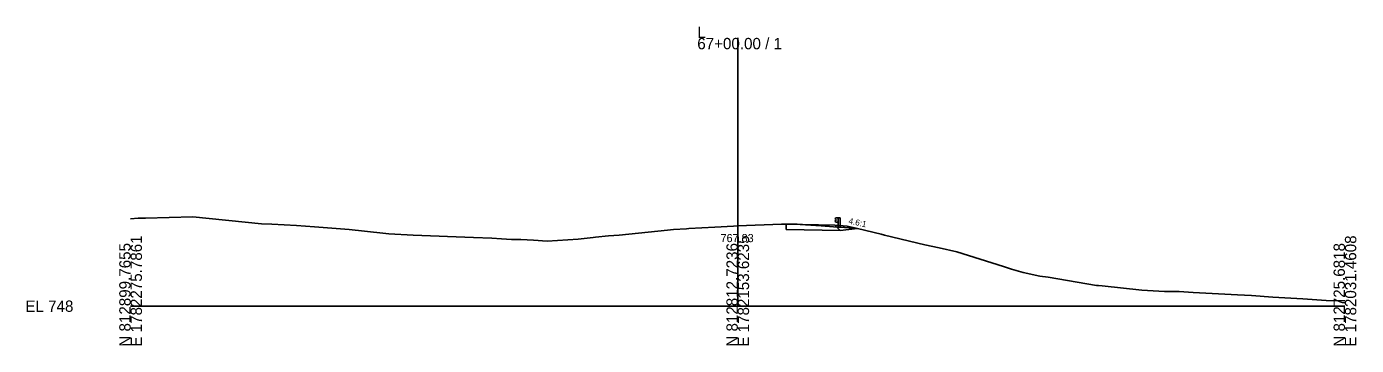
# Model space of a CAD drawing. Extents: x -26 to 7903, y -10 to 9573.
# Drawn here: x 2974.3 to 3302.8, y 7990.3 to 8069.1 of the extents above; entities that cross this region are included whole.
import ezdxf

# ---------------------------------------------------------------- set-up
doc = ezdxf.new("R2010")
doc.units = 0
for name, color, linetype in [('Exist Cross Section Cell', 7, 'Continuous'), ('Exist XS Center Line Elevation Label', 7, 'Continuous'), ('Exist XS Ground Line', 7, 'Continuous'), ('Prop XS Earthwork Shape', 7, 'Continuous'), ('Prop XS Finish Grade', 7, 'Continuous'), ('Prop XS Finish Grade Paved Shoulder', 7, 'Continuous'), ('Prop XS Guardrail', 7, 'Continuous'), ('Prop XS Pvmt Edge Slope', 7, 'Continuous'), ('Prop XS Side Slope Text', 7, 'Continuous'), ('Prop XS Subgrade Earthwork', 7, 'Continuous'), ('Scratch_Level_3', 7, 'Continuous'), ('Scratch_Level_6', 7, 'Continuous')]:
    doc.layers.add(name, color=color, linetype=linetype)

msp = doc.modelspace()

# ---------------------------------------------------------------- linework, layer by layer
at = {"layer": 'Exist Cross Section Cell'}
for p, q in [((3150, 8000), (3150, 8066.29)), ((3000, 8000), (3150, 8000)), ((3150, 8000), (3300, 8000))]:
    msp.add_line(p, q, dxfattribs=at)
at = {"layer": 'Exist XS Ground Line'}
for p, q in [((3000, 8021.62), (3001.85, 8021.76)), ((3001.85, 8021.76), (3003.72, 8021.76)), ((3003.72, 8021.76), (3015.37, 8022.1)), ((3015.37, 8022.1), (3032.34, 8020.38)), ((3032.34, 8020.38), (3034.88, 8020.23)), ((3034.88, 8020.23), (3041.01, 8019.97)), ((3041.01, 8019.97), (3045.44, 8019.63)), ((3045.44, 8019.63), (3053.97, 8018.96)), ((3137.88, 8019.17), (3144.35, 8019.53)), ((3144.35, 8019.53), (3148.92, 8019.79)), ((3148.92, 8019.79), (3150, 8019.83)), ((3150, 8019.83), (3160.81, 8020.24)), ((3160.81, 8020.24), (3164.68, 8020.23)), ((3164.68, 8020.23), (3165.39, 8020.18)), ((3165.39, 8020.18), (3170.61, 8019.83)), ((3170.61, 8019.83), (3173.64, 8019.59)), ((3173.64, 8019.59), (3176.35, 8019.43)), ((3053.97, 8018.96), (3062.33, 8018.03)), ((3062.33, 8018.03), (3063.8, 8017.87)), ((3063.8, 8017.87), (3069.8, 8017.57)), ((3069.8, 8017.57), (3084.68, 8016.96)), ((3084.68, 8016.96), (3089.28, 8016.81)), ((3089.28, 8016.81), (3091.66, 8016.62)), ((3091.66, 8016.62), (3094.1, 8016.5)), ((3094.1, 8016.5), (3096.44, 8016.51)), ((3096.44, 8016.51), (3099.54, 8016.32)), ((3099.54, 8016.32), (3102.89, 8016.1)), ((3102.89, 8016.1), (3105.43, 8016.23)), ((3105.43, 8016.23), (3110.6, 8016.55)), ((3110.6, 8016.55), (3114.31, 8016.98)), ((3114.31, 8016.98), (3114.85, 8017.04)), ((3114.85, 8017.04), (3118.07, 8017.4)), ((3118.07, 8017.4), (3120.73, 8017.58)), ((3120.73, 8017.58), (3132.67, 8018.76)), ((3132.67, 8018.76), (3134.15, 8018.93)), ((3134.15, 8018.93), (3137.33, 8019.13)), ((3137.33, 8019.13), (3137.88, 8019.17)), ((3176.35, 8019.43), (3179.58, 8019.19)), ((3179.58, 8019.19), (3185.43, 8017.79)), ((3185.43, 8017.79), (3186.24, 8017.58)), ((3186.24, 8017.58), (3196.19, 8015.16)), ((3196.19, 8015.16), (3199.79, 8014.43)), ((3199.79, 8014.43), (3204.16, 8013.45)), ((3204.16, 8013.45), (3215.66, 8009.77)), ((3215.66, 8009.77), (3217.65, 8009.14)), ((3217.65, 8009.14), (3220.49, 8008.34)), ((3220.49, 8008.34), (3224.67, 8007.43)), ((3224.67, 8007.43), (3226.69, 8007.13)), ((3226.69, 8007.13), (3238.67, 8005.15)), ((3238.67, 8005.15), (3239.16, 8005.08)), ((3239.16, 8005.08), (3240.04, 8005.01)), ((3240.04, 8005.01), (3249.79, 8003.98)), ((3249.79, 8003.98), (3255.39, 8003.62)), ((3255.39, 8003.62), (3259.07, 8003.6)), ((3259.07, 8003.6), (3262.53, 8003.41)), ((3262.53, 8003.41), (3273.44, 8002.78)), ((3273.44, 8002.78), (3276.92, 8002.62)), ((3276.92, 8002.62), (3282.22, 8002.21)), ((3282.22, 8002.21), (3289.62, 8001.78)), ((3289.62, 8001.78), (3295.36, 8001.38)), ((3295.36, 8001.38), (3300, 8001.33))]:
    msp.add_line(p, q, dxfattribs=at)
at = {"layer": 'Prop XS Earthwork Shape'}
msp.add_lwpolyline([(3175.28, 8018.72), (3179.58, 8019.19), (3176.35, 8019.43), (3173.64, 8019.59), (3170.61, 8019.83), (3165.39, 8020.18), (3164.68, 8020.23), (3162, 8020.24), (3162, 8018.99)], close=True, dxfattribs=at)
at = {"layer": 'Prop XS Finish Grade'}
for p, q in [((3174, 8020), (3177, 8019.76)), ((3177, 8019.76), (3179.58, 8019.19))]:
    msp.add_line(p, q, dxfattribs=at)
at = {"layer": 'Prop XS Finish Grade Paved Shoulder'}
msp.add_line((3162, 8020.24), (3174, 8020), dxfattribs=at)
at = {"layer": 'Prop XS Guardrail'}
for p, q in [((3174.03, 8021.67), (3174, 8021.61)), ((3174, 8021.61), (3174.03, 8021.55)), ((3174.03, 8021.06), (3174, 8021)), ((3174, 8021), (3174.03, 8020.94)), ((3174.32, 8021.87), (3174.03, 8021.67)), ((3174.03, 8021.55), (3174.32, 8021.35)), ((3174.32, 8021.26), (3174.03, 8021.06)), ((3174.03, 8020.94), (3174.32, 8020.74)), ((3174.82, 8021.87), (3174.32, 8021.87)), ((3174.32, 8021.35), (3174.32, 8021.26)), ((3174.32, 8020.74), (3174.82, 8020.74)), ((3175.32, 8021.87), (3174.82, 8021.87)), ((3174.82, 8021.87), (3174.82, 8019.37)), ((3175.32, 8019.37), (3175.32, 8021.87))]:
    msp.add_line(p, q, dxfattribs=at)
at = {"layer": 'Prop XS Pvmt Edge Slope'}
msp.add_line((3174, 8020), (3175.28, 8018.72), dxfattribs=at)
at = {"layer": 'Prop XS Subgrade Earthwork'}
for p, q in [((3162, 8018.99), (3162, 8020.24)), ((3162, 8018.99), (3175.28, 8018.72)), ((3175.28, 8018.72), (3179.58, 8019.19))]:
    msp.add_line(p, q, dxfattribs=at)
at = {"layer": 'Scratch_Level_3'}
for p, q in [((3177, 8019.76), (3174, 8020)), ((3174, 8020), (3175.28, 8018.72)), ((3179.58, 8019.19), (3177, 8019.76)), ((3175.28, 8018.72), (3179.58, 8019.19))]:
    msp.add_line(p, q, dxfattribs=at)
at = {"layer": 'Scratch_Level_6'}
for points in [[(3164.68, 8020.23), (3165.39, 8020.18), (3165.55, 8020.17), (3162, 8020.24)], [(3165.55, 8020.17), (3170.61, 8019.83), (3173.64, 8019.59), (3176.35, 8019.43), (3179.58, 8019.19), (3175.28, 8018.72), (3162, 8018.99), (3162, 8020.24)]]:
    msp.add_lwpolyline(points, close=True, dxfattribs=at)

# ---------------------------------------------------------------- texts
at = {"layer": 'Exist Cross Section Cell'}
for s, p in [('L', (3140, 8066.29)), ('67+00.00 / 1', (3140, 8063.49)), ('EL 748', (2974, 7998.6))]:
    msp.add_text(s, height=2.8, dxfattribs=at).set_placement(p)
for s, p in [('E 1782275.7861', (3002.8, 7990)), ('E 1782153.6235', (3152.8, 7990)), ('E 1782031.4608', (3302.8, 7990)), ('N 812899.7655', (3000, 7990)), ('N 812812.7236', (3150, 7990)), ('N 812725.6818', (3300, 7990))]:
    msp.add_text(s, height=2.8, rotation=90, dxfattribs=at).set_placement(p)
at = {"layer": 'Exist XS Center Line Elevation Label'}
msp.add_text('767.83', height=2, dxfattribs=at).set_placement((3145.75, 8015.83))
at = {"layer": 'Prop XS Side Slope Text'}
msp.add_text('4.6:1', height=1.5, rotation=347.6353, dxfattribs=at).set_placement((3177.27, 8020.42))

doc.saveas('drawing.dxf')
